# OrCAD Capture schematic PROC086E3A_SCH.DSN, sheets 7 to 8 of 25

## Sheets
7 08. CODEC-A STEREO_MIC 1: size C; title: CODEC-A STEREO MIC 1
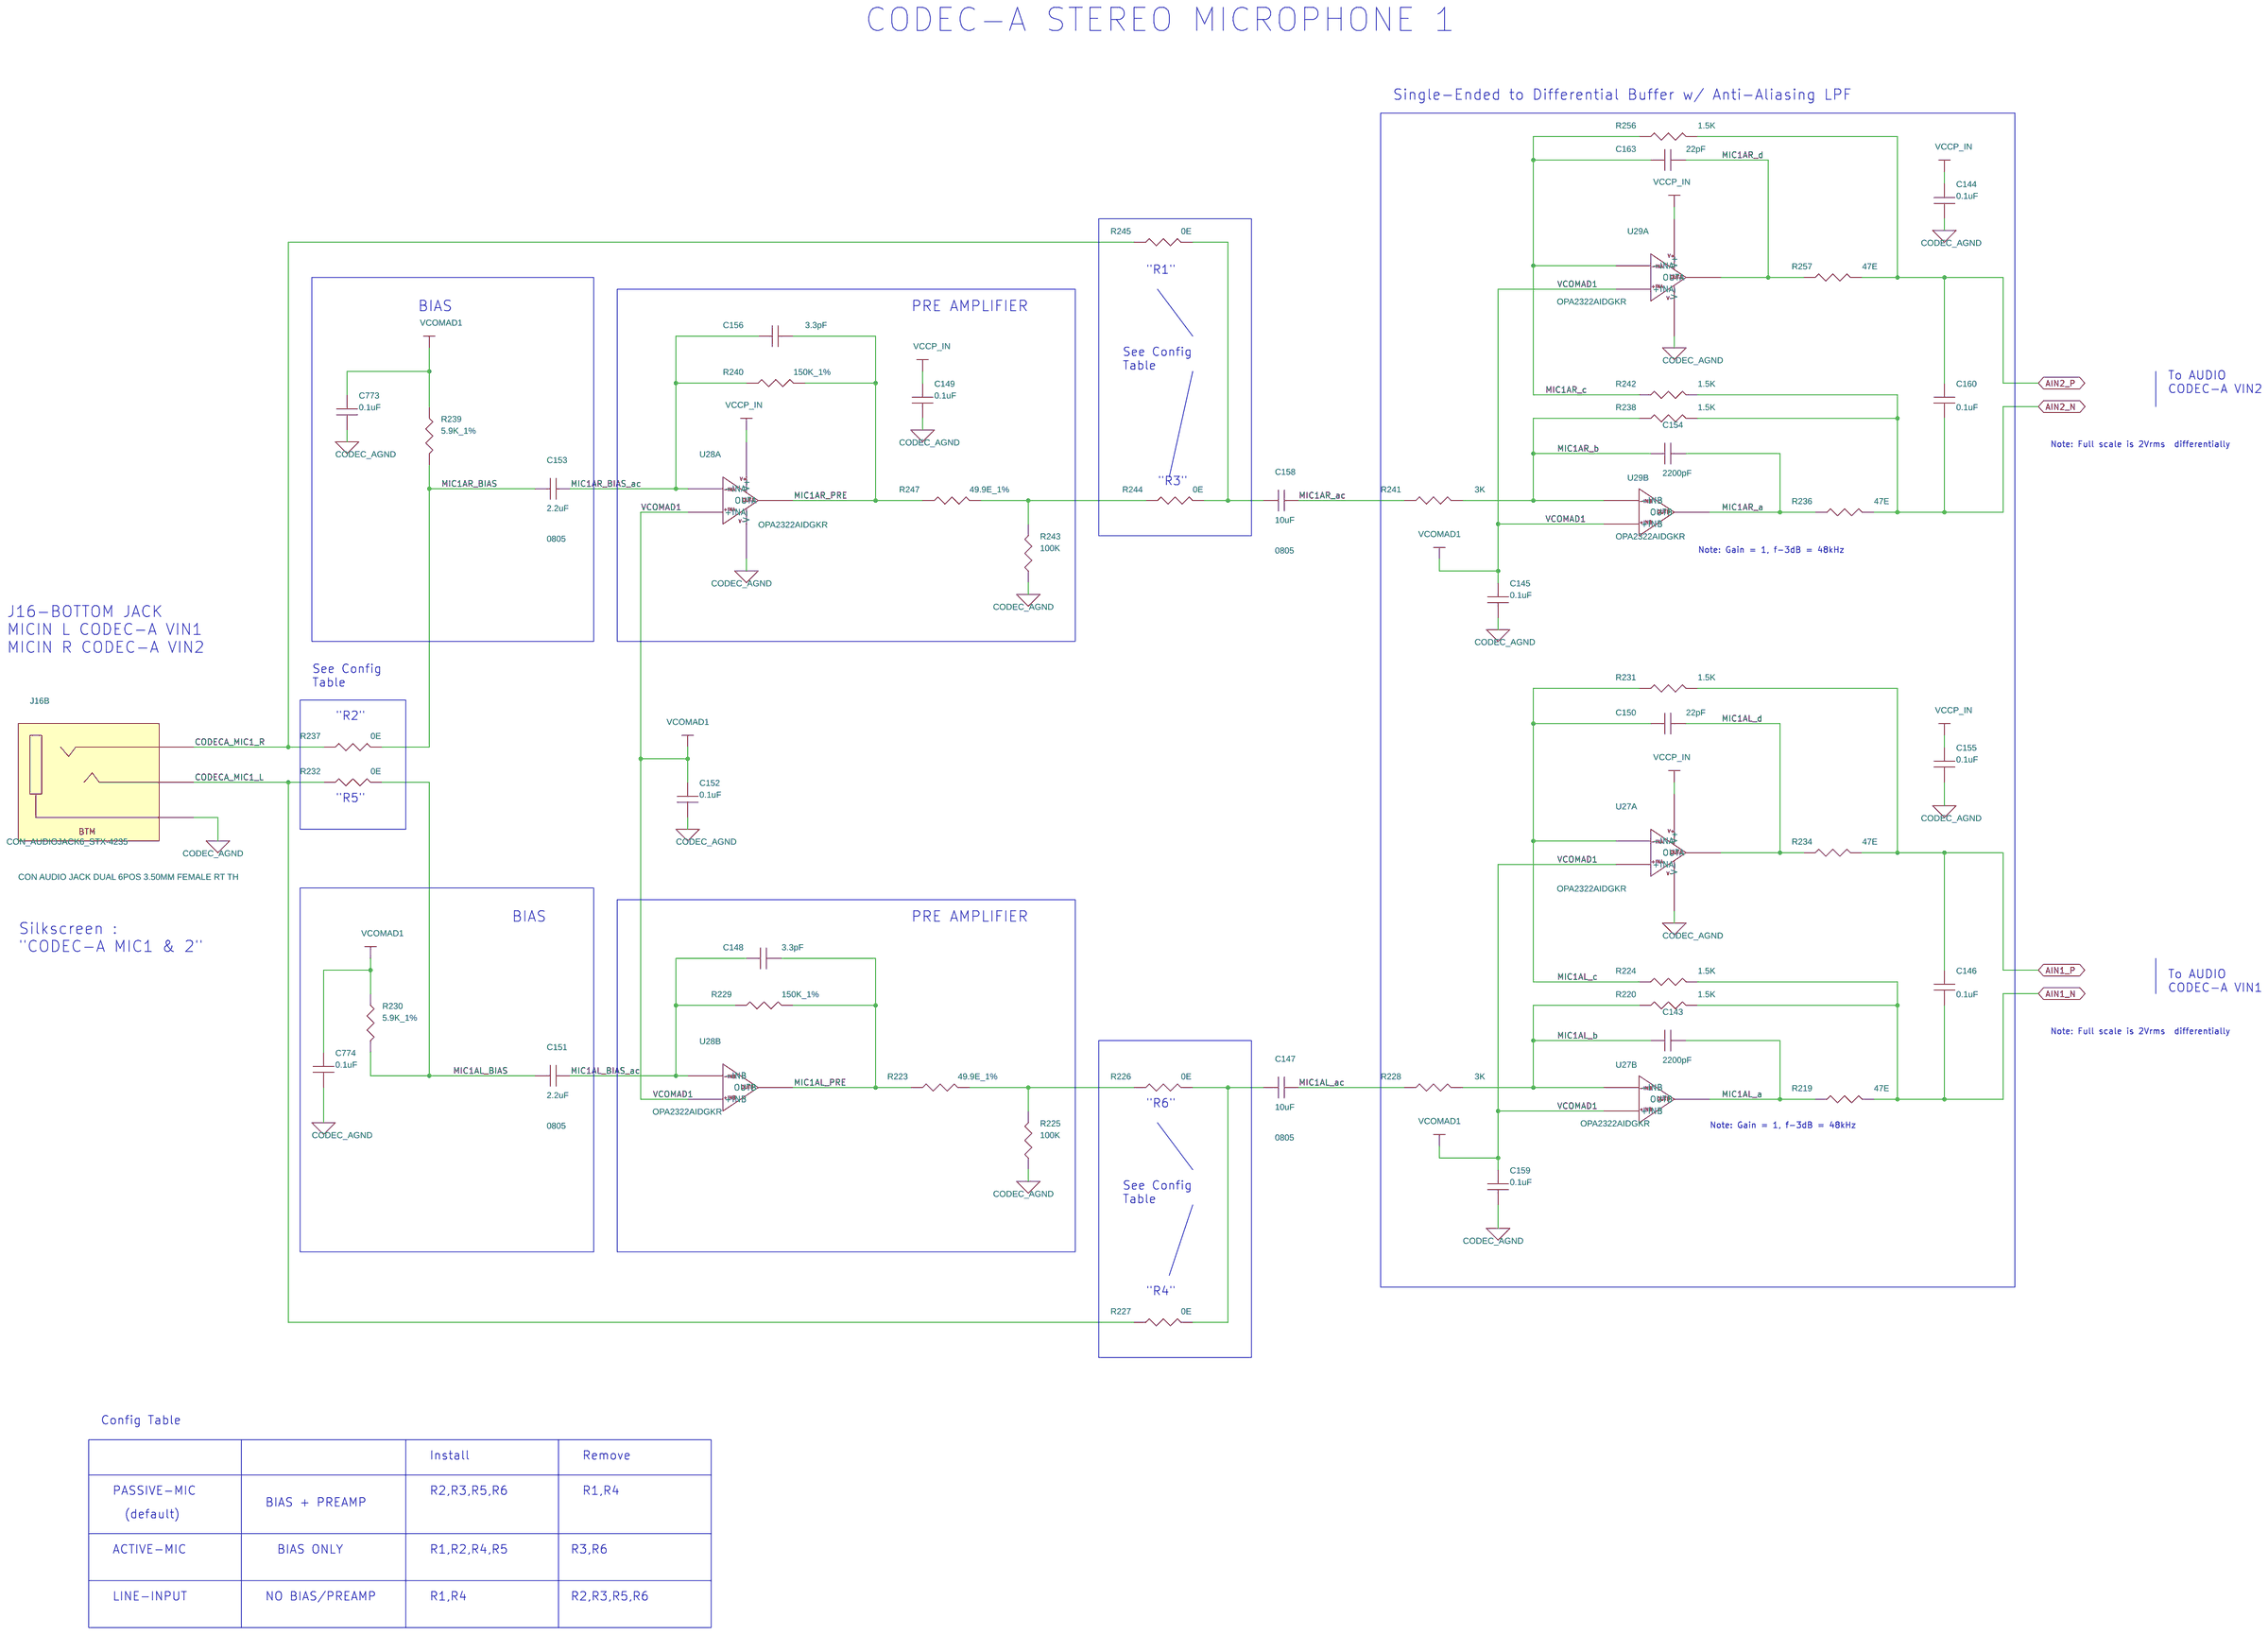
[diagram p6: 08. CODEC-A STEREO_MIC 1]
8 09. CODEC-A STEREO_MIC 2: size C; title: CODEC-A STEREO MIC 2
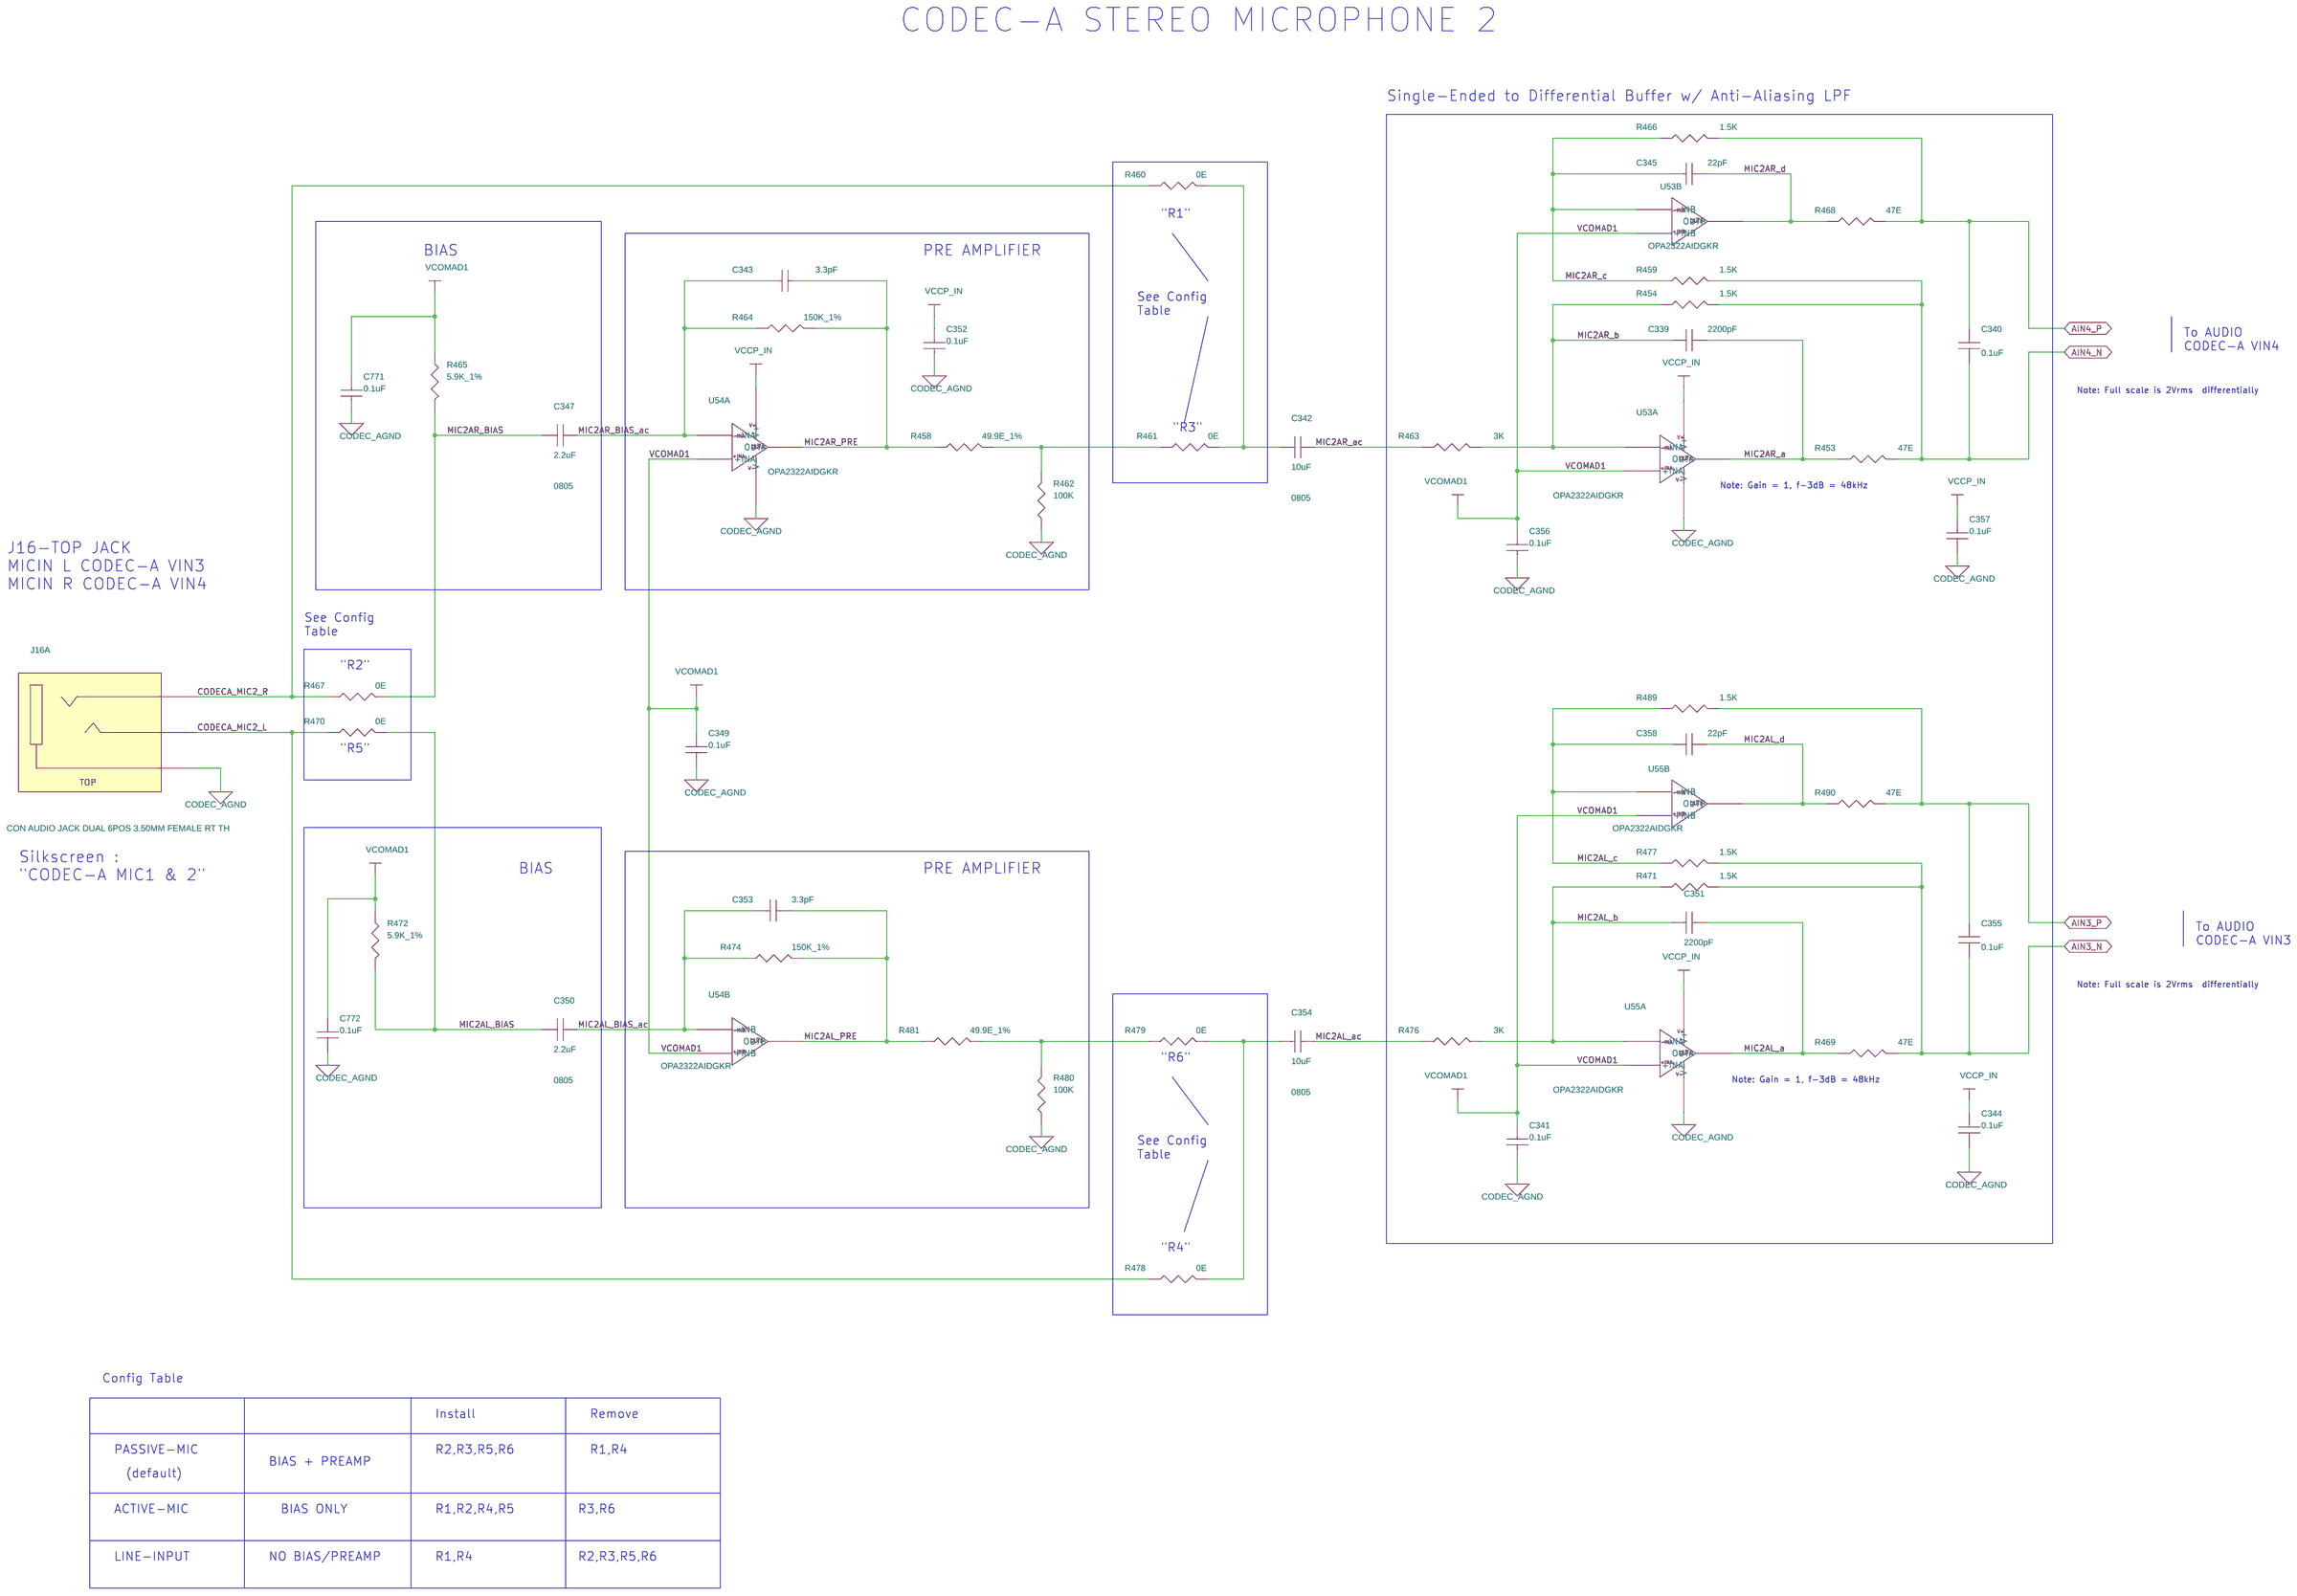
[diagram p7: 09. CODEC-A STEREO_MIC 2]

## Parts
sheet 08. CODEC-A STEREO_MIC 1
C143  2200pF  [CAP0402_0-75]
C144  0.1uF  [CAP0402_0-75]
C145  0.1uF  [CAP0402_0-75]
C146  0.1uF  [CAP0402_0-75]
C147  10uF  [CAP0805_1-5]
C148  3.3pF  [CAP0402_0-75]
C149  0.1uF  [CAP0402_0-75]
C150  22pF  [CAP0402_0-75]
C151  2.2uF  [CAP0805_1-5]
C152  0.1uF  [CAP0402_0-75]
C153  2.2uF  [CAP0805_1-5]
C154  2200pF  [CAP0402_0-75]
C155  0.1uF  [CAP0402_0-75]
C156  3.3pF  [CAP0402_0-75]
C158  10uF  [CAP0805_1-5]
C159  0.1uF  [CAP0402_0-75]
C160  0.1uF  [CAP0402_0-75]
C163  22pF  [CAP0402_0-75]
C773  0.1uF  [CAP0402_0-75]
C774  0.1uF  [CAP0402_0-75]
R219  47E  [RES0402_0-5]
R220  1.5K  [RES0402_0-5]
R223  49.9E_1%  [RES0402_0-5]
R224  1.5K  [RES0402_0-5]
R225  100K  [RES0402_0-5]
R226  0E  [RES0402_0-5]
R227  0E  [RES0402_0-5]
R228  3K  [RES0402_0-5]
R229  150K_1%  [RES0402_0-5]
R230  5.9K_1%  [RES0402_0-5]
R231  1.5K  [RES0402_0-5]
R232  0E  [RES0402_0-5]
R234  47E  [RES0402_0-5]
R236  47E  [RES0402_0-5]
R237  0E  [RES0402_0-5]
R238  1.5K  [RES0402_0-5]
R239  5.9K_1%  [RES0402_0-5]
R240  150K_1%  [RES0402_0-5]
R241  3K  [RES0402_0-5]
R242  1.5K  [RES0402_0-5]
R243  100K  [RES0402_0-5]
R244  0E  [RES0402_0-5]
R245  0E  [RES0402_0-5]
R247  49.9E_1%  [RES0402_0-5]
R256  1.5K  [RES0402_0-5]
R257  47E  [RES0402_0-5]
U27  OPA2322AIDGKR  [VSSOP8_25-59_120X120_1-1]  (sections A,B)
U28  OPA2322AIDGKR  [VSSOP8_25-59_120X120_1-1]  (sections A,B)
U29  OPA2322AIDGKR  [VSSOP8_25-59_120X120_1-1]  (sections A,B)
sheet 09. CODEC-A STEREO_MIC 2
C339  2200pF  [CAP0402_0-75]
C340  0.1uF  [CAP0402_0-75]
C341  0.1uF  [CAP0402_0-75]
C342  10uF  [CAP0805_1-5]
C343  3.3pF  [CAP0402_0-75]
C344  0.1uF  [CAP0402_0-75]
C345  22pF  [CAP0402_0-75]
C347  2.2uF  [CAP0805_1-5]
C349  0.1uF  [CAP0402_0-75]
C350  2.2uF  [CAP0805_1-5]
C351  2200pF  [CAP0402_0-75]
C352  0.1uF  [CAP0402_0-75]
C353  3.3pF  [CAP0402_0-75]
C354  10uF  [CAP0805_1-5]
C355  0.1uF  [CAP0402_0-75]
C356  0.1uF  [CAP0402_0-75]
C357  0.1uF  [CAP0402_0-75]
C358  22pF  [CAP0402_0-75]
C771  0.1uF  [CAP0402_0-75]
C772  0.1uF  [CAP0402_0-75]
J16  CON_AUDIOJACK6_STX-4235  [CON_AV6_STX-4235-3-3_S_R_T_26]  (sections A,B)
R453  47E  [RES0402_0-5]
R454  1.5K  [RES0402_0-5]
R458  49.9E_1%  [RES0402_0-5]
R459  1.5K  [RES0402_0-5]
R460  0E  [RES0402_0-5]
R461  0E  [RES0402_0-5]
R462  100K  [RES0402_0-5]
R463  3K  [RES0402_0-5]
R464  150K_1%  [RES0402_0-5]
R465  5.9K_1%  [RES0402_0-5]
R466  1.5K  [RES0402_0-5]
R467  0E  [RES0402_0-5]
R468  47E  [RES0402_0-5]
R469  47E  [RES0402_0-5]
R470  0E  [RES0402_0-5]
R471  1.5K  [RES0402_0-5]
R472  5.9K_1%  [RES0402_0-5]
R474  150K_1%  [RES0402_0-5]
R476  3K  [RES0402_0-5]
R477  1.5K  [RES0402_0-5]
R478  0E  [RES0402_0-5]
R479  0E  [RES0402_0-5]
R480  100K  [RES0402_0-5]
R481  49.9E_1%  [RES0402_0-5]
R489  1.5K  [RES0402_0-5]
R490  47E  [RES0402_0-5]
U53  OPA2322AIDGKR  [VSSOP8_25-59_120X120_1-1]  (sections A,B)
U54  OPA2322AIDGKR  [VSSOP8_25-59_120X120_1-1]  (sections A,B)
U55  OPA2322AIDGKR  [VSSOP8_25-59_120X120_1-1]  (sections A,B)

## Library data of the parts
C143 C154 C339 C351 = CAP: CAP CERAMIC 2200pF 50V 5% X7R 0402; Chkd/date: MANIRAJA/030619; Crtd /date: ALVY/310519; Custom_Duty: 15%; Customs_HS_Code: 85322990; Distributor_name: DIGIKEY; Distributor_part_number: 1276-1532-1-ND; Footprint Path: Y:\MIS_DATABASE\Library\ALTIUM_TOOL\PCB_FOOTPRINTS\Altium_Footprint_Lib.PcbLib; Height: 0.55MM; Library Path: Y:\MIS_DATABASE\Library\ALTIUM_TOOL\SCHEMATICS_PARTS\MS_DISCRETE_Library.schlib; Mfr_name: SAMSUNG; Mfr_part_number: CL05B222JB5NNNC; Mistral Part No: 120013090018-R; Package: 0402; Part_type: CAPACITORS\CERAMIC; Project: J7ES_SOM_DUAL-LEO_PMIC; RoHS: RoHS; Temperature: -55°C+125°C; Tolerance: 5%; Voltage: 50V; Wattage: NA; Weight: NA; Datasheet: Y:\MIS_DATABASE\DATASHEETS\CAPACITORS\CL05B222JB5NNNC.PDF
C144-C146 C149 C152 C155 C159 C160 C340 C341 C344 C349 C352 C355-C357 C771-C774 = CAP: CAP CERAMIC 0.1uF 50V 10% X7R 0402; Chkd/date: VASANTHA/281216; Crtd /date: CHAITHANYA/051011; Custom_Duty: 15%; Customs_HS_Code: 85322990; Distributor_name: DIGIKEY; Distributor_part_number: 445-173610-1-ND; Footprint Path: Y:\MIS_DATABASE\Library\ALTIUM_TOOL\PCB_FOOTPRINTS\Altium_Footprint_Lib.PcbLib; Height: 0.60MM; Library Path: Y:\MIS_DATABASE\Library\ALTIUM_TOOL\SCHEMATICS_PARTS\MS_DISCRETE_Library.schlib; Mfr_name: TDK CORPORATION; Mfr_part_number: C1005X7R1H104K050BE; Mistral Part No: 120011100014-R; Package: 0402; Part_type: CAPACITORS\CERAMIC; Project: VP-4000-BASE-BOARD; RoHS: RoHS; Temperature: -55°C+125°C; Tolerance: 10%; Voltage: 50V; Wattage: NA; Weight: 0.65mg; Datasheet: Y:\MIS_DATABASE\DATASHEETS\CAPACITORS\TDK_C-SER_FEB19.PDF
C147 C158 C342 C354 = CAP: CAP CERAMIC 10uF 16V 10% X5R 0805; Chkd/date: SHREESHAIL/220506; Crtd /date: MAZHAR/150506; Custom_Duty: 15%; Customs_HS_Code: 85322990; Distributor_name: DIGIKEY; Distributor_part_number: 490-3886-1-ND; Footprint Path: Y:\MIS_DATABASE\Library\ALTIUM_TOOL\PCB_FOOTPRINTS\Altium_Footprint_Lib.PcbLib; Height: 1.35MM; Library Path: Y:\MIS_DATABASE\Library\ALTIUM_TOOL\SCHEMATICS_PARTS\MS_DISCRETE_Library.schlib; Mfr_name: MURATA; Mfr_part_number: GRM21BR61C106KE15L; Mistral Part No: 120009030205-R; Package: 0805; Part_type: CAPACITORS\CERAMIC; Project: VOCERA; RoHS: RoHS; Temperature: -55°C+85°C; Tolerance: 10%; Voltage: 16V; Wattage: NA; Weight: 9.5mg; Datasheet: Y:\MIS_DATABASE\DATASHEETS\CAPACITORS\MURATA-GXX-SER_NOV17.PDF
C148 C156 C343 C353 = CAP: CAP CERAMIC 3.3pF 50V 0.25pF C0G(NP0) 0402; Chkd/date: SHREESHAIL/281105; Crtd /date: MAZHAR/211005; Custom_Duty: 15%; Customs_HS_Code: 85322990; Distributor_name: DIGIKEY; Distributor_part_number: 478-1064-1-ND; Footprint Path: Y:\MIS_DATABASE\Library\ALTIUM_TOOL\PCB_FOOTPRINTS\Altium_Footprint_Lib.PcbLib; Height: 0.56MM; Library Path: Y:\MIS_DATABASE\Library\ALTIUM_TOOL\SCHEMATICS_PARTS\MS_DISCRETE_Library.schlib; Mfr_name: AVX CORPORATION; Mfr_part_number: 04025A3R3CAT2A; Mistral Part No: 120009030354-R; Package: 0402; Part_type: CAPACITORS\CERAMIC; Project: EPDA_CORE; RoHS: RoHS; Temperature: -55°C+125°C; Tolerance: 0.25pF%; Voltage: 50V; Wattage: NA; Weight: 0.65mg; Datasheet: Y:\MIS_DATABASE\DATASHEETS\CAPACITORS\AVX_MLC.PDF
C150 C163 C345 C358 = CAP: CAP CERAMIC 22pF 50V 5% C0G(NP0) 0402; Chkd/date: MANIRAJA/060619; Crtd /date: MANIRAJA/060619; Custom_Duty: 15%; Customs_HS_Code: 85322990; Distributor_name: DIGIKEY; Distributor_part_number: 1276-1116-1-ND; Footprint Path: Y:\MIS_DATABASE\Library\ALTIUM_TOOL\PCB_FOOTPRINTS\Altium_Footprint_Lib.PcbLib; Height: 0.55MM; Library Path: Y:\MIS_DATABASE\Library\ALTIUM_TOOL\SCHEMATICS_PARTS\MS_DISCRETE_Library.schlib; Mfr_name: SAMSUNG; Mfr_part_number: CL05C220JB5NNNC; Mistral Part No: 120014100023-R; Package: 0402; Part_type: CAPACITORS\CERAMIC; Project: J7ES_SOM_DUAL-LEO_PMIC; RoHS: RoHS; Temperature: -55°C+125°C; Tolerance: 5%; Voltage: 50V; Wattage: NA; Weight: 0.65mg; Datasheet: Y:\MIS_DATABASE\DATASHEETS\CAPACITORS\CL05C220JB5NNNC.PDF
C151 C153 C347 C350 = CAP: CAP CERAMIC 2.2uF 50V 20% X7R 0805; Chkd/date: MANIRAJA/241018; Crtd /date: ALVY/241018; Custom_Duty: 15%; Customs_HS_Code: 85322990; Distributor_name: DIGIKEY; Distributor_part_number: 445-172488-1-ND; Footprint Path: Y:\MIS_DATABASE\Library\ALTIUM_TOOL\PCB_FOOTPRINTS\Altium_Footprint_Lib.PcbLib; Height: 1.50MM; Library Path: Y:\MIS_DATABASE\Library\ALTIUM_TOOL\SCHEMATICS_PARTS\MS_DISCRETE_Library.schlib; Mfr_name: TDK CORPORATION; Mfr_part_number: C2012X7R1H225M125AE; Mistral Part No: 120018100054-R; Package: 0805; Part_type: CAPACITORS\CERAMIC; Project: TI_J7ES_EVM_CP; RoHS: RoHS; Temperature: -55°C+125°C; Tolerance: 20%; Voltage: 50V; Wattage: NA; Weight: 5.5mg; Datasheet: Y:\MIS_DATABASE\DATASHEETS\CAPACITORS\TDK-CAP-E-SER.PDF
R219 R234 R236 R257 R453 R468 R469 R490 = RESISTOR: RES 47E 1/16W 5% 0402; Chkd/date: MANIRAJA/250319; Crtd /date: MANIRAJA/250319; Custom_Duty: 15%; Customs_HS_Code: 85332119; Distributor_name: DIGIKEY; Distributor_part_number: 311-47JRCT-ND; Footprint Path: Y:\MIS_DATABASE\Library\ALTIUM_TOOL\PCB_FOOTPRINTS\Altium_Footprint_Lib.PcbLib; Height: 0.40MM; Library Path: Y:\MIS_DATABASE\Library\ALTIUM_TOOL\SCHEMATICS_PARTS\MS_DISCRETE_Library.schlib; Mfr_name: YAGEO AMERICA; Mfr_part_number: RC0402JR-0747RL; Mistral Part No: 110019040221-R; Package: 0402; Part_type: RESISTORS\FIXED; Project: POWERBOX; RoHS: RoHS; Temperature: -55°C+155°C; Tolerance: 5%; Voltage: NA; Wattage: 1/16W; Weight: 0.65mg; Datasheet: Y:\MIS_DATABASE\DATASHEETS\RESISTORS\RCXXXXL-SER_MAR18.PDF
R220 R224 R231 R238 R242 R256 R454 R459 R466 R471 R477 R489 = RESISTOR: RES 1.5K 1/16W 5% 0402; Chkd/date: MANIRAJA/310718; Crtd /date: BAVISH/021210; Custom_Duty: 15%; Customs_HS_Code: 85332119; Distributor_name: DIGIKEY; Distributor_part_number: 311-1.5KJRCT-ND; Footprint Path: Y:\MIS_DATABASE\Library\ALTIUM_TOOL\PCB_FOOTPRINTS\Altium_Footprint_Lib.PcbLib; Height: 0.40MM; Library Path: Y:\MIS_DATABASE\Library\ALTIUM_TOOL\SCHEMATICS_PARTS\MS_DISCRETE_Library.schlib; Mfr_name: YAGEO AMERICA; Mfr_part_number: RC0402JR-071K5L; Mistral Part No: 110010120012-R; Package: 0402; Part_type: RESISTORS\FIXED; Project: TE4; RoHS: RoHS; Temperature: -55°C+155°C; Tolerance: 5%; Voltage: NA; Wattage: 1/16W; Weight: 0.65mg; Datasheet: Y:\MIS_DATABASE\DATASHEETS\RESISTORS\RCXXXXL-SER_MAR18.PDF
R223 R247 R458 R481 = RESISTOR: RES 49.9E 1/10W 1% 0402; Chkd/date: VASANTHA/201216; Crtd /date: MAZHAR/201005; Custom_Duty: 15%; Customs_HS_Code: 85332119; Distributor_name: DIGIKEY; Distributor_part_number: P49.9LCT-ND; Footprint Path: Y:\MIS_DATABASE\Library\ALTIUM_TOOL\PCB_FOOTPRINTS\Altium_Footprint_Lib.PcbLib; Height: 0.40MM; Library Path: Y:\MIS_DATABASE\Library\ALTIUM_TOOL\SCHEMATICS_PARTS\MS_DISCRETE_Library.schlib; Mfr_name: PANASONIC-ECG; Mfr_part_number: ERJ-2RKF49R9X; Mistral Part No: 110009030897-R; Package: 0402; Part_type: RESISTORS\FIXED; Project: RED EYE; RoHS: RoHS; Temperature: -55°C+155°C; Tolerance: 1%; Voltage: NA; Wattage: 1/10W; Weight: 0.8mg; Datasheet: Y:\MIS_DATABASE\DATASHEETS\RESISTORS\PAN-ERJSER_NOV17.PDF
R225 R243 R462 R480 = RESISTOR: RES 100K 1/16W 5% 0402; Assembly_Instruction: DNI; Chkd/date: VASANTHA/130516; Crtd /date: VASANTHA/130516; Custom_Duty: 15%; Customs_HS_Code: 85332119; Distributor_name: DIGIKEY; Distributor_part_number: A121521CT-ND; Footprint Path: Y:\MIS_DATABASE\Library\ALTIUM_TOOL\PCB_FOOTPRINTS\Altium_Footprint_Lib.PcbLib; Height: 0.40MM; Library Path: Y:\MIS_DATABASE\Library\ALTIUM_TOOL\SCHEMATICS_PARTS\MS_DISCRETE_Library.schlib; Mfr_name: TE CONNECTIVITY; Mfr_part_number: CRG0402J100K/10; Mistral Part No: 110019040062-R; Package: 0402; Part_type: RESISTORS\FIXED; Project: TMDXCSK368; RoHS: RoHS; Temperature: -55°C+125°C; Tolerance: 5%; Voltage: NA; Wattage: 1/16W; Weight: 0.65mg; Datasheet: Y:\MIS_DATABASE\DATASHEETS\RESISTORS\CRG-SERIES.PDF
R226 R232 R237 R244 R461 R467 R470 R479 = RESISTOR: RES 0E 1/10W JUMPER 0402; Chkd/date: VASANTHA/061216; Crtd /date: NAVEED/201014; Custom_Duty: 15%; Customs_HS_Code: 85332119; Distributor_name: DIGIKEY; Distributor_part_number: P0.0JCT-ND; Footprint Path: Y:\MIS_DATABASE\Library\ALTIUM_TOOL\PCB_FOOTPRINTS\Altium_Footprint_Lib.PcbLib; Height: 0.40MM; IBISSP_MODLES: VALUE REPEATING 2 TIME; Library Path: Y:\MIS_DATABASE\Library\ALTIUM_TOOL\SCHEMATICS_PARTS\MS_DISCRETE_Library.schlib; Mfr_name: PANASONIC-ECG; Mfr_part_number: ERJ-2GE0R00X; Mistral Part No: 110018030052-R; Package: 0402; Part_type: RESISTORS\FIXED; Project: AEGIS POM; RoHS: RoHS; Temperature: -55°C+155°C; Tolerance: NA; Voltage: NA; Wattage: 1/10W; Weight: 0.8mg; Datasheet: Y:\MIS_DATABASE\DATASHEETS\RESISTORS\PAN-ERJSER_NOV17.PDF
R227 R245 R460 R478 = RESISTOR: RES 0E 1/10W JUMPER 0402; Assembly_Instruction: DNI; Chkd/date: VASANTHA/061216; Crtd /date: NAVEED/201014; Custom_Duty: 15%; Customs_HS_Code: 85332119; Distributor_name: DIGIKEY; Distributor_part_number: P0.0JCT-ND; Footprint Path: Y:\MIS_DATABASE\Library\ALTIUM_TOOL\PCB_FOOTPRINTS\Altium_Footprint_Lib.PcbLib; Height: 0.40MM; IBISSP_MODLES: VALUE REPEATING 2 TIME; Library Path: Y:\MIS_DATABASE\Library\ALTIUM_TOOL\SCHEMATICS_PARTS\MS_DISCRETE_Library.schlib; Mfr_name: PANASONIC-ECG; Mfr_part_number: ERJ-2GE0R00X; Mistral Part No: 110018030052-R; Package: 0402; Part_type: RESISTORS\FIXED; Project: AEGIS POM; RoHS: RoHS; Temperature: -55°C+155°C; Tolerance: NA; Voltage: NA; Wattage: 1/10W; Weight: 0.8mg; Datasheet: Y:\MIS_DATABASE\DATASHEETS\RESISTORS\PAN-ERJSER_NOV17.PDF
R228 R241 R463 R476 = RESISTOR: RES 3K 1/10W 5% 0402; Chkd/date: MAZHAR/150709; Crtd /date: MAZHAR/110907; Custom_Duty: 15%; Customs_HS_Code: 85332119; Distributor_name: DIGIKEY; Distributor_part_number: P3.0KJCT-ND; Footprint Path: Y:\MIS_DATABASE\Library\ALTIUM_TOOL\PCB_FOOTPRINTS\Altium_Footprint_Lib.PcbLib; Height: 0.40MM; Library Path: Y:\MIS_DATABASE\Library\ALTIUM_TOOL\SCHEMATICS_PARTS\MS_DISCRETE_Library.schlib; Mfr_name: PANASONIC-ECG; Mfr_part_number: ERJ-2GEJ302X; Mistral Part No: 110009030764-R; Package: 0402; Part_type: RESISTORS\FIXED; Project: TELEMETRY ENCODER; RoHS: RoHS; Temperature: -55°C+155°C; Tolerance: 5%; Voltage: NA; Wattage: 1/10W; Weight: 0.8mg; Datasheet: Y:\MIS_DATABASE\DATASHEETS\RESISTORS\PAN-ERJSER_NOV17.PDF
R229 R240 R464 R474 = RESISTOR: RES 150K 1/10W 1% 0402; Chkd/date: SHREESHAIL/200906; Crtd /date: MAZHAR/190906; Custom_Duty: 15%; Customs_HS_Code: 85332119; Distributor_name: DIGIKEY; Distributor_part_number: P150KLCT-ND; Footprint Path: Y:\MIS_DATABASE\Library\ALTIUM_TOOL\PCB_FOOTPRINTS\Altium_Footprint_Lib.PcbLib; Height: 0.40MM; Library Path: Y:\MIS_DATABASE\Library\ALTIUM_TOOL\SCHEMATICS_PARTS\MS_DISCRETE_Library.schlib; Mfr_name: PANASONIC-ECG; Mfr_part_number: ERJ-2RKF1503X; Mistral Part No: 110009030336-R; Package: 0402; Part_type: RESISTORS\FIXED; Project: SM2_AFE; RoHS: RoHS; Temperature: -55°C+155°C; Tolerance: 1%; Voltage: NA; Wattage: 1/10W; Weight: 0.8mg; Datasheet: Y:\MIS_DATABASE\DATASHEETS\RESISTORS\PAN-ERJSER_NOV17.PDF
R230 R239 R465 R472 = RESISTOR: RES 5.9K 1/10W 1% 0402; Chkd/date: MAZHAR/251110; Crtd /date: BAVISH/251110; Custom_Duty: 15%; Customs_HS_Code: 85332119; Distributor_name: DIGIKEY; Distributor_part_number: P5.90KLCT-ND; Footprint Path: Y:\MIS_DATABASE\Library\ALTIUM_TOOL\PCB_FOOTPRINTS\Altium_Footprint_Lib.PcbLib; Height: 0.40MM; Library Path: Y:\MIS_DATABASE\Library\ALTIUM_TOOL\SCHEMATICS_PARTS\MS_DISCRETE_Library.schlib; Mfr_name: PANASONIC-ECG; Mfr_part_number: ERJ-2RKF5901X; Mistral Part No: 110010110029-R; Package: 0402; Part_type: RESISTORS\FIXED; Project: CENTAURUS; RoHS: RoHS; Temperature: -55°C+155°C; Tolerance: 1%; Voltage: NA; Wattage: 1/10W; Weight: 0.8mg; Datasheet: Y:\MIS_DATABASE\DATASHEETS\RESISTORS\PAN-ERJSER_NOV17.PDF
U27-U29 U53-U55 = OPA2350UA_SOIC8: IC 20MHz 1.8V LOW NOISE RRI/O CMOS OPAMP VSSOP8; Chkd/date: MANIRAJA/161018; Crtd /date: ALVY/161018; Custom_Duty: 15%; Customs_HS_Code: 85423100; Distributor_name: DIGIKEY; Distributor_part_number: 296-41349-1-ND; Footprint Path: Y:\MIS_DATABASE\Library\ALTIUM_TOOL\PCB_FOOTPRINTS\Altium_Footprint_Lib.PcbLib; Height: 1.10MM; Library Path: Y:\MIS_DATABASE\Library\ALTIUM_TOOL\SCHEMATICS_PARTS\MS_OPAMP_Library.schlib; Mfr_name: TEXAS INSTRUMENTS; Mistral Part No: 140118100019-R; Package: VSSOP8; Part_type: ICS\ANALOG\OPAMP; Project: TI_J7ES_EVM_CP; RoHS: RoHS; Temperature: -40°C+125°C; Tolerance: NA; Voltage: NA; Wattage: NA; Weight: 26.5mg; Datasheet: Y:\MIS_DATABASE\DATASHEETS\ICS\OPAMP\OPA2322XX.PDF
J16 = CON_AUDIOJACK6_STX-4235-3_3: CON AUDIO JACK DUAL 6POS 3.50MM FEMALE RT TH; Chkd/date: MANIRAJA/090818; Crtd /date: ALVY/080818; Custom_Duty: 24%; Customs_HS_Code: 85369090; Distributor_name: MOUSER; Distributor_part_number: 806-STX-4235-3/3-N; Footprint Path: Y:\MIS_DATABASE\Library\ALTIUM_TOOL\PCB_FOOTPRINTS\Altium_Footprint_Lib.PcbLib; Height: 26.00MM; Library Path: Y:\MIS_DATABASE\Library\ALTIUM_TOOL\SCHEMATICS_PARTS\MS_CONNECTOR_Library.schlib; Library Ref: CON_AUDIOJACK6_STX-4235-3/3; Mfr_name: KYCON; Mfr_part_number: STX-4235-3/3-N; Mistral Part No: 150018080005-R; Package: THRU-HOLE; Part_type: CONNECTOR\JACK; Project: TI_J7ES_EVM_FUSION2_SER_CAP; RoHS: RoHS; Temperature: -25°C+85°C; Tolerance: NA; Voltage: NA; Wattage: NA; Weight: NA; Datasheet: Y:\MIS_DATABASE\DATASHEETS\CONNECTORS\STX-4235-3-3-N.PDF

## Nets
DGND: C144.2 C145.2 C149.2 C152.2 C155.2 C159.2 C341.2 C344.2 C349.2 C352.2 C356.2 C357.2 C771.2 C772.2 C773.2 C774.2 J16.1A J16.1B R225.1 R243.1 R462.1 R480.1 U27.4(V-) U28.4(V-) U29.4(V-) U53.4(V-) U54.4(V-) U55.4(V-) ; also on sheet 5 6 9 10 11 12 13 14 15 16 17 18 19 20 21 22 23 25
VCCP_IN: C144.1 C149.1 C155.1 C344.1 C352.1 C357.1 U27.8(V+) U28.8(V+) U29.8(V+) U53.8(V+) U54.8(V+) U55.8(V+) ; also on sheet 6 10 11 12 22 23
AIN1_N: C146.2 R219.2 R220.2 R224.2 ; also on sheet 23
AIN1_P: C146.1 R231.2 R234.2 ; also on sheet 23
AIN2_N: C160.2 R236.2 R238.2 R242.2 ; also on sheet 23
AIN2_P: C160.1 R256.2 R257.2 ; also on sheet 23
AIN3_N: C355.2 R469.2 R471.2 R477.2 ; also on sheet 23
AIN3_P: C355.1 R489.2 R490.2 ; also on sheet 23
AIN4_N: C340.2 R453.2 R454.2 R459.2 ; also on sheet 23
AIN4_P: C340.1 R466.2 R468.2 ; also on sheet 23
CODECA_MIC1_L: J16.5B R227.1 R232.1
CODECA_MIC1_R: J16.2B R237.1 R245.1
CODECA_MIC2_L: J16.5A R470.1 R478.1
CODECA_MIC2_R: J16.2A R460.1 R467.1
MIC1AL_a: C143.2 R219.1 U27.7(OUTB)
MIC1AL_ac: C147.1 R228.1
MIC1AL_b: C143.1 R220.1 R228.2 U27.6(-INB)
MIC1AL_BIAS: C151.2 R230.2 R232.2
MIC1AL_BIAS_ac: C148.1 C151.1 R229.1 U28.6(-INB)
MIC1AL_c: C150.1 R224.1 R231.1 U27.2(-INA)
MIC1AL_d: C150.2 R234.1 U27.1(OUTA)
MIC1AL_PRE: C148.2 R223.1 R229.2 U28.7(OUTB)
MIC1AR_a: C154.2 R236.1 U29.7(OUTB)
MIC1AR_ac: C158.1 R241.1
MIC1AR_b: C154.1 R238.1 R241.2 U29.6(-INB)
MIC1AR_BIAS: C153.2 R237.2 R239.2
MIC1AR_BIAS_ac: C153.1 C156.1 R240.1 U28.2(-INA)
MIC1AR_c: C163.1 R242.1 R256.1 U29.2(-INA)
MIC1AR_d: C163.2 R257.1 U29.1(OUTA)
MIC1AR_PRE: C156.2 R240.2 R247.1 U28.1(OUTA)
MIC2AL_a: C351.2 R469.1 U55.1(OUTA)
MIC2AL_ac: C354.1 R476.1
MIC2AL_b: C351.1 R471.1 R476.2 U55.2(-INA)
MIC2AL_BIAS: C350.2 R470.2 R472.2
MIC2AL_BIAS_ac: C350.1 C353.1 R474.1 U54.6(-INB)
MIC2AL_c: C358.1 R477.1 R489.1 U55.6(-INB)
MIC2AL_d: C358.2 R490.1 U55.7(OUTB)
MIC2AL_PRE: C353.2 R474.2 R481.1 U54.7(OUTB)
MIC2AR_a: C339.2 R453.1 U53.1(OUTA)
MIC2AR_ac: C342.1 R463.1
MIC2AR_b: C339.1 R454.1 R463.2 U53.2(-INA)
MIC2AR_BIAS: C347.2 R465.2 R467.2
MIC2AR_BIAS_ac: C343.1 C347.1 R464.1 U54.2(-INA)
MIC2AR_c: C345.1 R459.1 R466.1 U53.6(-INB)
MIC2AR_d: C345.2 R468.1 U53.7(OUTB)
MIC2AR_PRE: C343.2 R458.1 R464.2 U54.1(OUTA)
VCOMAD1: C145.1 C152.1 C159.1 C341.1 C349.1 C356.1 C771.1 C772.1 C773.1 C774.1 R230.1 R239.1 R465.1 R472.1 U27.3(+INA) U27.5(+INB) U28.3(+INA) U28.5(+INB) U29.3(+INA) U29.5(+INB) U53.3(+INA) U53.5(+INB) U54.3(+INA) U54.5(+INB) U55.3(+INA) U55.5(+INB) ; also on sheet 6 23
N23981776: C147.2 R226.2 R227.2
N23985739: C158.2 R244.2 R245.2
N23990208: R243.2 R244.1 R247.2
N23990244: R223.2 R225.2 R226.1
N24479449: C342.2 R460.2 R461.2
N24479767: R458.2 R461.1 R462.2
N24480253: R479.1 R480.2 R481.2
N24480259: C354.2 R478.2 R479.2

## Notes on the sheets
sheet 7
- CODEC-A STEREO MICROPHONE 1
- Single-Ended to Differential Buffer w/ Anti-Aliasing LPF
- "R1"
- BIAS
- PRE AMPLIFIER
- See Config
  Table
- To AUDIO
  CODEC-A VIN2
- Note: Full scale is 2Vrms  differentially
- "R3"
- Note: Gain = 1, f-3dB = 48kHz
- J16-BOTTOM JACK
  MICIN L CODEC-A VIN1
  MICIN R CODEC-A VIN2
- See Config
  Table
- "R2"
- "R5"
- BIAS
- PRE AMPLIFIER
- Silkscreen :
  "CODEC-A MIC1 & 2"
- To AUDIO
  CODEC-A VIN1
- Note: Full scale is 2Vrms  differentially
- "R6"
- Note: Gain = 1, f-3dB = 48kHz
- See Config
  Table
- "R4"
- Config Table
- Install
- Remove
- PASSIVE-MIC
- R2,R3,R5,R6
- R1,R4
- (default)
- BIAS + PREAMP
- ACTIVE-MIC
- BIAS ONLY
- R1,R2,R4,R5
- R3,R6
- LINE-INPUT
- NO BIAS/PREAMP
- R1,R4
- R2,R3,R5,R6
sheet 8
- CODEC-A STEREO MICROPHONE 2
- Single-Ended to Differential Buffer w/ Anti-Aliasing LPF
- "R1"
- BIAS
- PRE AMPLIFIER
- See Config
  Table
- To AUDIO
  CODEC-A VIN4
- Note: Full scale is 2Vrms  differentially
- "R3"
- Note: Gain = 1, f-3dB = 48kHz
- J16-TOP JACK
  MICIN L CODEC-A VIN3
  MICIN R CODEC-A VIN4
- See Config
  Table
- "R2"
- "R5"
- Silkscreen :
  "CODEC-A MIC1 & 2"
- BIAS
- PRE AMPLIFIER
- To AUDIO
  CODEC-A VIN3
- Note: Full scale is 2Vrms  differentially
- "R6"
- Note: Gain = 1, f-3dB = 48kHz
- See Config
  Table
- "R4"
- Config Table
- Install
- Remove
- PASSIVE-MIC
- R2,R3,R5,R6
- R1,R4
- BIAS + PREAMP
- (default)
- ACTIVE-MIC
- BIAS ONLY
- R1,R2,R4,R5
- R3,R6
- LINE-INPUT
- NO BIAS/PREAMP
- R1,R4
- R2,R3,R5,R6
